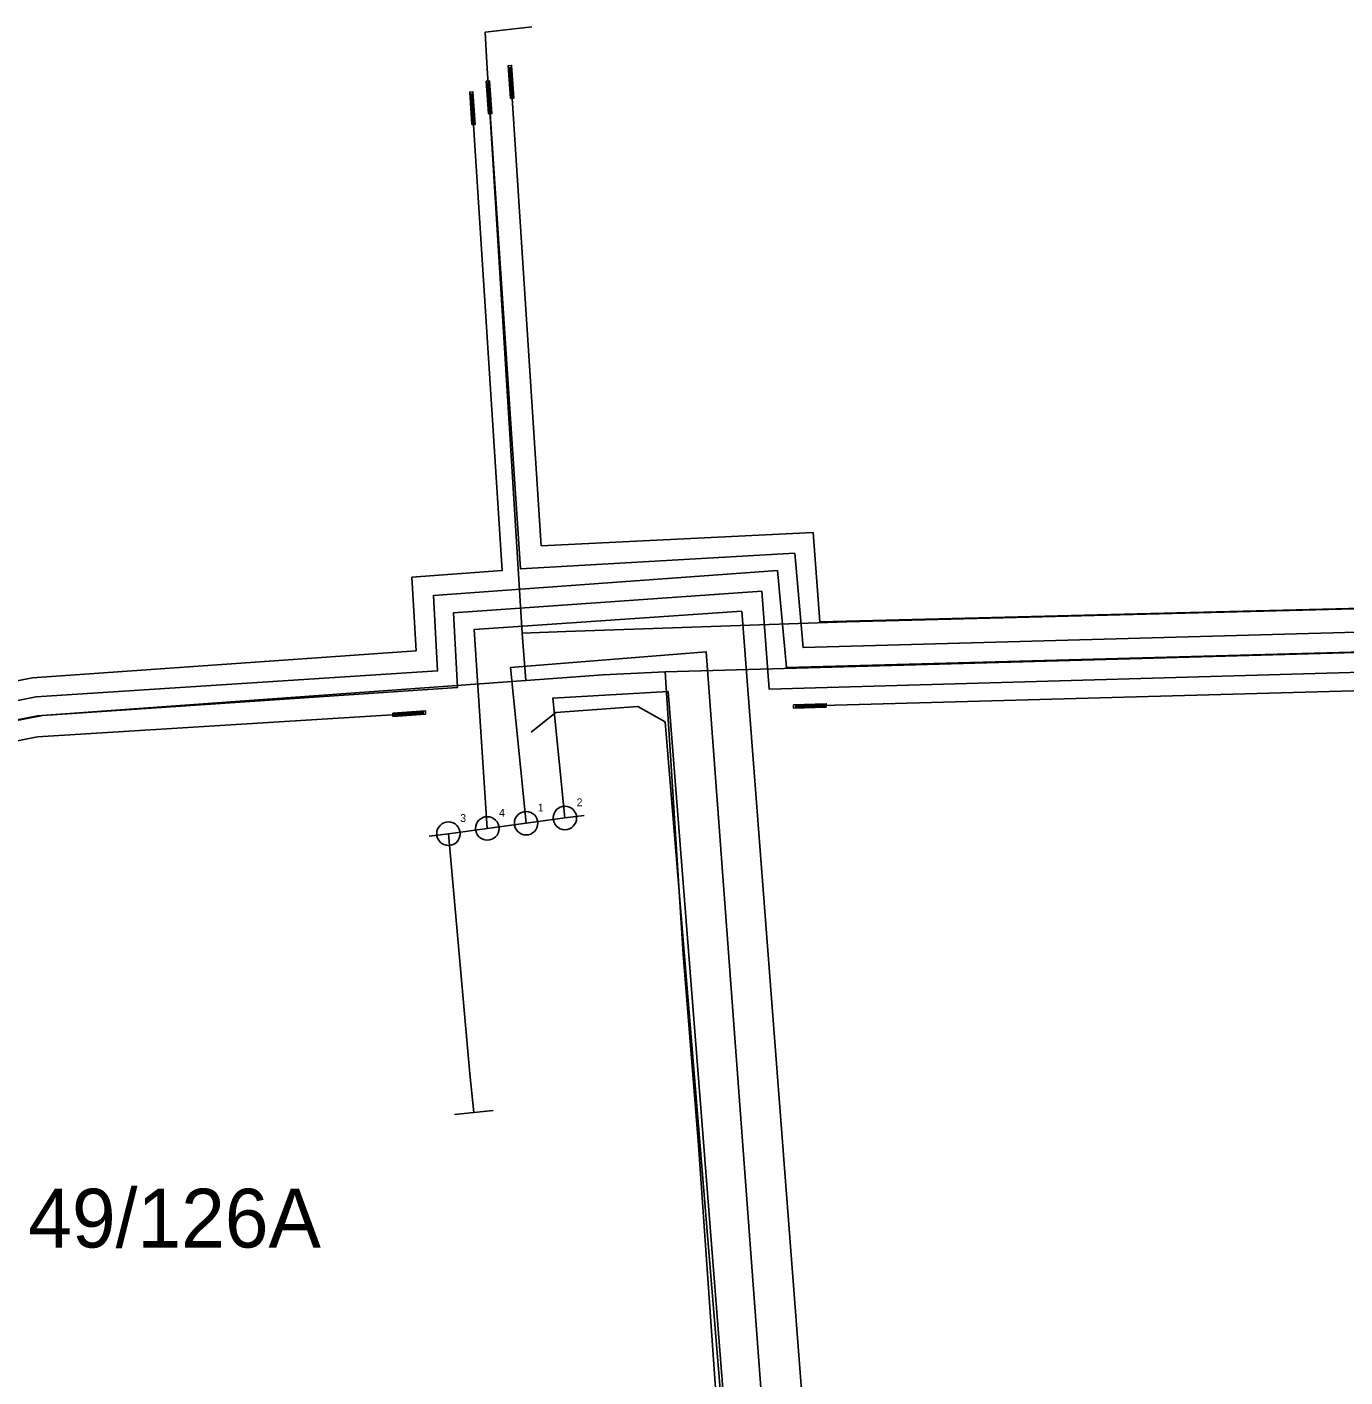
# Model space of a CAD drawing. Extents: x -744800 to -744528, y -1052473 to -1052336.
# Drawn here: x -744644.94 to -744611.28, y -1052370.65 to -1052336.18 of the extents above; entities that cross this region are included whole.
import ezdxf

# ---------------------------------------------------------------- set-up
doc = ezdxf.new("R2010")
doc.units = 0
for name, color, linetype in [('NN_CISLO_VYVODU', 7, 'Continuous'), ('NN_KABEL_INSTALACE_RIS_PROVOZ', 7, 'Continuous'), ('NN_KABELOVE_VEDENI_PROVOZ', 7, 'Continuous'), ('NN_KABELOVE_VEDENI_VYRAZENO', 7, 'Continuous'), ('NN_PRIPOJNICE_RIS', 7, 'Continuous'), ('NN_PRIPOJOVACI_MISTO', 7, 'Continuous'), ('NN_RIS', 7, 'Continuous'), ('NN_SPOJKA', 7, 'Continuous'), ('NN_VYVODY', 7, 'Continuous'), ('TRASA_KABELU_NN', 7, 'Continuous'), ('TRASA_KABELU_NN_PROVOZ', 7, 'Continuous')]:
    doc.layers.add(name, color=color, linetype=linetype)

msp = doc.modelspace()

# ---------------------------------------------------------------- linework, layer by layer
at = {"layer": 'NN_KABEL_INSTALACE_RIS_PROVOZ'}
msp.add_line((-744633.632, -1052362.908), (-744634.174, -1052356.776), dxfattribs=at)
at = {"layer": 'NN_KABELOVE_VEDENI_PROVOZ'}
for points in [[(-744633.183, -1052356.642), (-744633.521, -1052351.56), (-744626.684, -1052351.094), (-744623.911, -1052387.31), (-744623.568, -1052390.367), (-744623.165, -1052395.131), (-744564.248, -1052388.055), (-744552.516, -1052404.718), (-744538.787, -1052394.869), (-744542.655, -1052389.688), (-744543.251, -1052380.647), (-744543.648, -1052379.434), (-744543.791, -1052377.578), (-744544.659, -1052368.082), (-744547.073, -1052354.821), (-744543.518, -1052347.643), (-744535.387, -1052345.83), (-744534.333, -1052350.257)], [(-744632.192, -1052356.508), (-744632.59, -1052352.533), (-744627.595, -1052352.131), (-744624.97, -1052387.437), (-744628.541, -1052390.068), (-744661.572, -1052393.905), (-744661.969, -1052380.543), (-744664.088, -1052353.097), (-744690.819, -1052354.788), (-744690.316, -1052362.699), (-744697.407, -1052363.175), (-744697.161, -1052368.506), (-744701.87, -1052368.837)], [(-744631.201, -1052356.374), (-744631.51, -1052353.316), (-744628.568, -1052353.147), (-744626.044, -1052385.278), (-744628.324, -1052385.438), (-744628.417, -1052384.441)]]:
    msp.add_lwpolyline(points, dxfattribs=at)
at = {"layer": 'NN_KABELOVE_VEDENI_VYRAZENO'}
for points in [[(-744535.335, -1052343.068), (-744536.509, -1052337.369), (-744584.547, -1052350.894), (-744625.118, -1052352.025), (-744625.33, -1052349.612), (-744632.336, -1052350.014), (-744633.137, -1052338)], [(-744579.716, -1052345.471), (-744578.794, -1052348.676), (-744584.496, -1052350.356), (-744624.695, -1052351.369), (-744624.864, -1052349.083), (-744631.807, -1052349.422), (-744632.574, -1052337.603)], [(-744633.56, -1052338.275), (-744632.802, -1052350.057), (-744635.109, -1052350.226), (-744635.003, -1052352.11), (-744644.8, -1052352.796), (-744662.199, -1052356.204), (-744664.887, -1052353.685), (-744690.17, -1052355.317), (-744689.776, -1052363.13), (-744695.539, -1052363.606)], [(-744535.795, -1052343.306), (-744536.843, -1052338.052), (-744584.484, -1052351.418), (-744625.541, -1052352.533), (-744625.774, -1052350.057), (-744634.558, -1052350.692), (-744634.453, -1052352.618), (-744644.706, -1052353.278), (-744662.54, -1052356.847), (-744665.582, -1052354.733), (-744689.095, -1052356.294), (-744688.812, -1052363.65), (-744689.117, -1052364.084), (-744695.043, -1052364.655)], [(-744695.064, -1052365.586), (-744688.714, -1052365.142), (-744687.72, -1052363.83), (-744688.058, -1052357.204), (-744666.87, -1052355.829), (-744663.039, -1052357.374), (-744644.539, -1052353.754), (-744633.944, -1052353.041), (-744634.05, -1052351.136), (-744626.176, -1052350.586), (-744625.986, -1052353.084), (-744584.452, -1052351.895), (-744537.287, -1052338.607), (-744536.224, -1052343.513)], [(-744536.621, -1052343.878), (-744537.589, -1052339.29), (-744584.277, -1052352.387), (-744624.918, -1052353.514)], [(-744635.205, -1052353.712), (-744644.666, -1052354.305), (-744663.06, -1052357.966), (-744667.421, -1052356.929), (-744687, -1052358.22), (-744686.64, -1052365.735), (-744695.085, -1052366.497)]]:
    msp.add_lwpolyline(points, dxfattribs=at)
at = {"layer": 'NN_PRIPOJNICE_RIS'}
msp.add_lwpolyline([(-744634.669, -1052356.843), (-744634.174, -1052356.776), (-744633.183, -1052356.642), (-744632.192, -1052356.508), (-744631.201, -1052356.374), (-744630.705, -1052356.307)], dxfattribs=at)
at = {"layer": 'NN_PRIPOJOVACI_MISTO'}
for p, q in [((-744633.529, -1052363.893), (-744633.632, -1052362.908)), ((-744633.036, -1052363.841), (-744634.021, -1052363.944))]:
    msp.add_line(p, q, dxfattribs=at)
at = {"layer": 'NN_SPOJKA'}
for points in [[(-744632.589, -1052337.997), (-744632.647, -1052337.163), (-744632.563, -1052337.157), (-744632.505, -1052337.991), (-744632.533, -1052337.993), (-744632.587, -1052337.215), (-744632.615, -1052337.217), (-744632.561, -1052337.995)], [(-744633.152, -1052338.394), (-744633.21, -1052337.56), (-744633.126, -1052337.554), (-744633.068, -1052338.388), (-744633.096, -1052338.39), (-744633.15, -1052337.612), (-744633.178, -1052337.614), (-744633.124, -1052338.392)], [(-744633.575, -1052338.669), (-744633.633, -1052337.835), (-744633.549, -1052337.829), (-744633.491, -1052338.663), (-744633.519, -1052338.665), (-744633.573, -1052337.887), (-744633.601, -1052337.889), (-744633.547, -1052338.667)], [(-744635.599, -1052353.697), (-744634.765, -1052353.639), (-744634.759, -1052353.723), (-744635.593, -1052353.781), (-744635.595, -1052353.753), (-744634.817, -1052353.699), (-744634.819, -1052353.671), (-744635.597, -1052353.725)], [(-744624.525, -1052353.542), (-744625.36, -1052353.571), (-744625.363, -1052353.488), (-744624.528, -1052353.458), (-744624.527, -1052353.486), (-744625.306, -1052353.514), (-744625.305, -1052353.542), (-744624.526, -1052353.514)]]:
    msp.add_lwpolyline(points, close=True, dxfattribs=at)
at = {"layer": 'NN_VYVODY'}
for centre in [(-744631.201, -1052356.374), (-744634.174, -1052356.776), (-744633.183, -1052356.642), (-744632.192, -1052356.508)]:
    msp.add_circle(centre, 0.3, dxfattribs=at)
at = {"layer": 'TRASA_KABELU_NN'}
for p, q in [((-744632.293, -1052351.658), (-744632.196, -1052352.864)), ((-744632.196, -1052352.864), (-744630.222, -1052352.721))]:
    msp.add_line(p, q, dxfattribs=at)
for points in [[(-744632.043, -1052336.175), (-744633.237, -1052336.309), (-744633.191, -1052337.09), (-744632.293, -1052351.658)], [(-744628.642, -1052352.639), (-744584.523, -1052351.406), (-744536.828, -1052337.999), (-744531.954, -1052363.41)], [(-744632.293, -1052351.658), (-744631.177, -1052351.616), (-744624.002, -1052351.364), (-744597.741, -1052350.69)], [(-744667.699, -1052358.163), (-744666.677, -1052358.075), (-744664.755, -1052357.699), (-744644.667, -1052353.764), (-744632.196, -1052352.864)]]:
    msp.add_lwpolyline(points, dxfattribs=at)
at = {"layer": 'TRASA_KABELU_NN_PROVOZ'}
msp.add_line((-744630.222, -1052352.721), (-744628.642, -1052352.639), dxfattribs=at)
for points in [[(-744628.2, -1052385.252), (-744626.254, -1052385.13), (-744626.9, -1052376.968), (-744627.09, -1052374.703), (-744627.788, -1052364.727), (-744628.177, -1052359.852), (-744628.642, -1052352.639)], [(-744625.81, -1052388.87), (-744625.8, -1052388.03), (-744626.17, -1052380.19), (-744626.58, -1052378.13), (-744626.38, -1052376.7), (-744626.4, -1052375.4), (-744626.94, -1052374.18), (-744627.03, -1052373.02), (-744627.21, -1052371.28), (-744627.78, -1052364.34), (-744628.64, -1052353.92), (-744629.34, -1052353.53), (-744631.43, -1052353.68), (-744632.06, -1052354.18)]]:
    msp.add_lwpolyline(points, dxfattribs=at)

# ---------------------------------------------------------------- texts
at = {"layer": 'NN_CISLO_VYVODU'}
for s, p in [('4', (-744632.883, -1052356.342)), ('1', (-744631.892, -1052356.208)), ('2', (-744630.901, -1052356.074)), ('3', (-744633.874, -1052356.476))]:
    msp.add_text(s, height=0.2, dxfattribs=at).set_placement(p)
at = {"layer": 'NN_RIS'}
msp.add_text('49/126A', height=1.5, dxfattribs=at).set_placement((-744644.905, -1052367.344))

doc.saveas('drawing.dxf')
